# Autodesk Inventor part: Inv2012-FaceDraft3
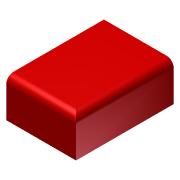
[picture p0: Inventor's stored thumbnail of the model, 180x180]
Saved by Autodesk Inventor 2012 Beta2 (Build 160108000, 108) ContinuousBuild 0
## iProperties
Created: 2011-02
Part Number: Inv2012-FaceDraft3
Material: Default
Document SubType Name: Modeling
Designer: ehttln
Density: 1 g/cm^3
Author: ehttln
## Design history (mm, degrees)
sketch "Sketch1"
  geometry: L1 (-23.559, -52.24)-(26.441, -52.24); L2 (26.441, -52.24)-(26.441, 17.76); L3 (26.441, 17.76)-(-23.559, 17.76); L4 (-23.559, 17.76)-(-23.559, -52.24); 1 further point
  constraints: 8 end point, 2 parallel, 1 horizontal, 1 perpendicular
  dimensions: "d0" = 50 distance of L2.end L3.end; "d1" = 70 distance of L3.end L1.start
extrude "Extrusion1" new body sketch "Sketch1" distance "d2" = 27.5; taper "d3" = 0 deg
fillet "Fillet6" dims "d43" = 5
feature "FaceDraft13" dims angle "d47" = 30 deg
body "Solid1"
